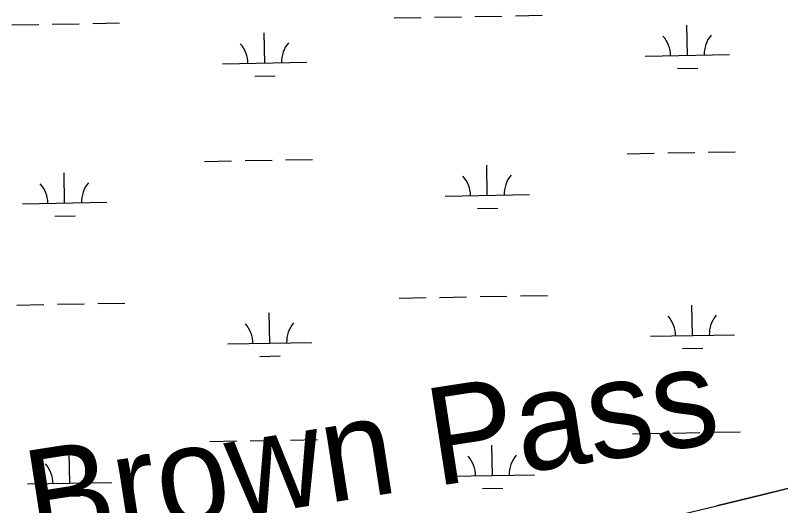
# Model space of a CAD drawing. Extents: x 3957609 to 3995875, y 234277 to 260273.
# Drawn here: x 3969026 to 3969934, y 256465 to 257047 of the extents above; entities that cross this region are included whole.
import ezdxf

# ---------------------------------------------------------------- set-up
doc = ezdxf.new("R2010")
doc.units = 0
for name, color, linetype in [('V-RIVR-IDEN', 7, 'Continuous'), ('V-TOPO-SHOR', 7, 'Continuous'), ('V-WETL-SWMP', 7, 'Continuous')]:
    doc.layers.add(name, color=color, linetype=linetype)

msp = doc.modelspace()

# ---------------------------------------------------------------- linework, layer by layer
at = {"layer": 'V-TOPO-SHOR'}
msp.add_lwpolyline([(3969809.264, 256452.607), (3969858.541, 256464.559), (3969914.13, 256477.711), (3969994.551, 256498.021), (3970055.651, 256515.132), (3970141.194, 256537.824), (3970256.3, 256569.658), (3970331.599, 256587.59), (3970405.714, 256605.521), (3970503.479, 256631.004), (3970604.003, 256657.675), (3970669.432, 256678.345), (3970742.745, 256702.584), (3970806.196, 256726.406), (3970878.328, 256748.274), (3970976.487, 256774.153), (3971061.631, 256798.815), (3971137.323, 256817.538), (3971269.775, 256853.359), (3971338.766, 256869.305), (3971513.403, 256915.09)], dxfattribs=at)
at = {"layer": 'V-WETL-SWMP'}
for p, q in [((3969475.389, 257043.729), (3969507.384, 257044.311)), ((3969523.381, 257044.601), (3969555.376, 257045.183)), ((3969571.373, 257045.474), (3969603.368, 257046.056)), ((3969619.365, 257046.347), (3969651.36, 257046.928)), ((3969021.556, 257035.477), (3969053.551, 257036.058)), ((3969069.548, 257036.349), (3969101.543, 257036.931)), ((3969117.54, 257037.222), (3969149.535, 257037.804)), ((3969823.57, 256999.309), (3969822.915, 257035.303)), ((3969321.745, 256990.185), (3969321.09, 257026.179)), ((3969773.578, 256998.4), (3969873.562, 257000.218)), ((3969271.753, 256989.276), (3969371.737, 256991.094)), ((3969811.852, 256983.663), (3969835.849, 256984.099)), ((3969310.027, 256974.538), (3969334.023, 256974.974)), ((3969752.273, 256882.562), (3969784.267, 256883.144)), ((3969800.265, 256883.435), (3969832.259, 256884.016)), ((3969848.257, 256884.307), (3969880.252, 256884.889)), ((3969250.448, 256873.437), (3969282.442, 256874.019)), ((3969298.44, 256874.31), (3969330.434, 256874.892)), ((3969346.432, 256875.182), (3969378.426, 256875.764)), ((3969586.08, 256833.102), (3969585.426, 256869.096)), ((3969084.255, 256823.978), (3969083.601, 256859.972)), ((3969536.089, 256832.193), (3969636.072, 256834.011)), ((3969034.264, 256823.069), (3969134.247, 256824.887)), ((3969574.363, 256817.456), (3969598.359, 256817.892)), ((3969072.538, 256808.331), (3969096.534, 256808.767)), ((3969481.437, 256711.109), (3969513.432, 256711.69)), ((3969529.429, 256711.981), (3969561.424, 256712.563)), ((3969577.421, 256712.854), (3969609.416, 256713.436)), ((3969625.413, 256713.727), (3969657.408, 256714.308)), ((3969027.604, 256702.857), (3969059.599, 256703.438)), ((3969075.596, 256703.729), (3969107.591, 256704.311)), ((3969123.588, 256704.602), (3969155.583, 256705.184)), ((3969829.618, 256666.689), (3969828.964, 256702.683)), ((3969327.793, 256657.565), (3969327.138, 256693.559)), ((3969779.626, 256665.78), (3969879.61, 256667.598)), ((3969277.801, 256656.656), (3969377.785, 256658.474)), ((3969817.901, 256651.043), (3969841.897, 256651.479)), ((3969316.075, 256641.918), (3969340.072, 256642.354)), ((3969854.305, 256551.687), (3969886.3, 256552.269)), ((3969352.48, 256542.562), (3969384.475, 256543.144)), ((3969758.321, 256549.942), (3969790.315, 256550.524)), ((3969806.313, 256550.815), (3969838.307, 256551.396)), ((3969256.496, 256540.817), (3969288.49, 256541.399)), ((3969304.488, 256541.69), (3969336.482, 256542.272)), ((3969592.128, 256500.482), (3969591.474, 256536.476)), ((3969090.303, 256491.358), (3969089.649, 256527.352)), ((3969542.137, 256499.573), (3969642.12, 256501.391)), ((3969994.551, 256498.022), (3969914.13, 256477.711)), ((3969040.312, 256490.449), (3969140.295, 256492.267)), ((3969580.411, 256484.836), (3969604.407, 256485.272)), ((3969078.586, 256475.711), (3969102.582, 256476.147)), ((3969914.13, 256477.711), (3969858.542, 256464.559))]:
    msp.add_line(p, q, dxfattribs=at)
for centre, start, end in [((3969768.328, 256998.78), 0.269879, 41.813537), ((3969878.795, 257000.788), 140.269876, 181.813534), ((3969266.502, 256989.655), 0.269879, 41.813537), ((3969376.97, 256991.664), 140.269876, 181.813534), ((3969530.838, 256832.573), 0.269879, 41.813537), ((3969641.306, 256834.581), 140.269876, 181.813534), ((3969029.013, 256823.448), 0.269879, 41.813537), ((3969139.481, 256825.457), 140.269876, 181.813534), ((3969774.376, 256666.16), 0.269879, 41.813537), ((3969884.843, 256668.168), 140.269876, 181.813534), ((3969272.551, 256657.035), 0.269879, 41.813537), ((3969383.018, 256659.044), 140.269876, 181.813534), ((3969536.886, 256499.953), 0.269879, 41.813537), ((3969647.354, 256501.961), 140.269876, 181.813534), ((3969035.061, 256490.828), 0.269879, 41.813537), ((3969145.529, 256492.837), 140.269876, 181.813534)]:
    msp.add_arc(centre, 35.246, start, end, dxfattribs=at)

# ---------------------------------------------------------------- texts
at = {"layer": 'V-RIVR-IDEN'}
msp.add_text('Joe Brown Pass', height=115.99977, rotation=8.817004, dxfattribs=at).set_placement((3968757.992, 256368.627))

doc.saveas('drawing.dxf')
